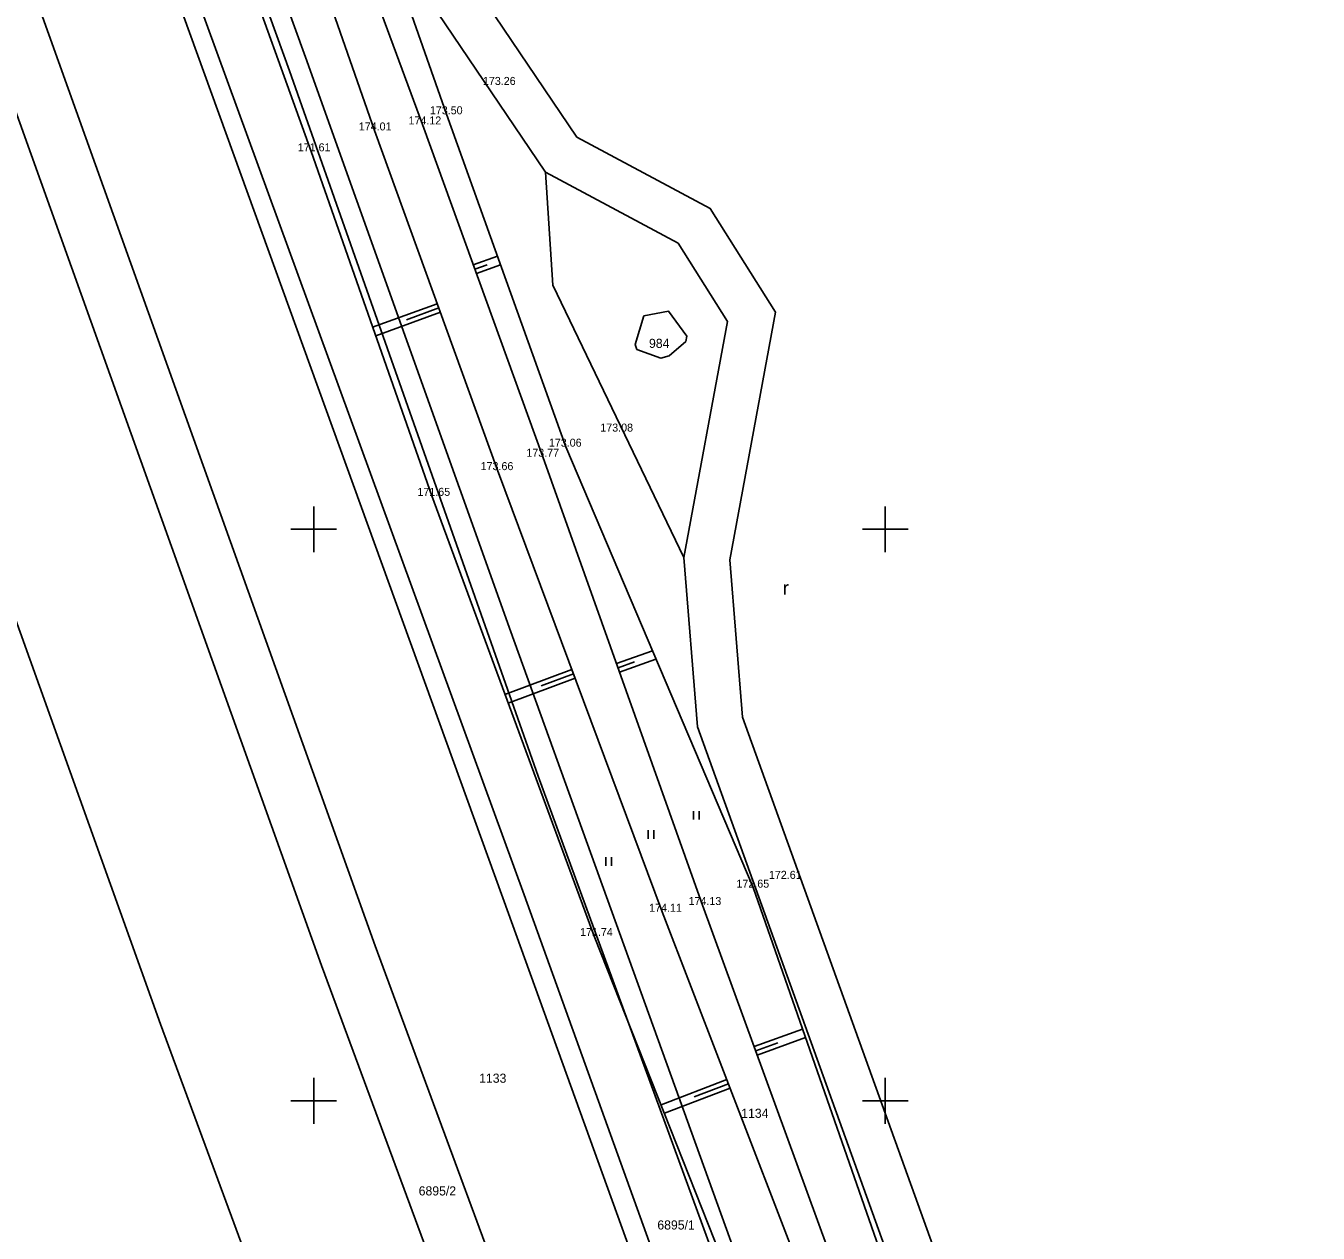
# Model space of a CAD drawing. Extents: x -612546 to -611926, y -1201932 to -1200444.
# Drawn here: x -612425.2 to -612312.1, y -1200761.6 to -1200656 of the extents above; entities that cross this region are included whole.
import ezdxf

# ---------------------------------------------------------------- set-up
doc = ezdxf.new("R2010")
doc.units = 0
for name, color, linetype in [('14 hrana pata svahu', 7, 'Continuous'), ('15 šrafy', 7, 'Continuous'), ('61 legenda křížky', 7, 'Continuous'), ('Hranice parcel', 7, 'Continuous'), ('Parcelní čísla', 7, 'Continuous'), ('Vnitřní kresba', 7, 'Continuous'), ('Vrstva 36', 7, 'Continuous'), ('výška bodu', 7, 'Continuous')]:
    doc.layers.add(name, color=color, linetype=linetype)

msp = doc.modelspace()

# ---------------------------------------------------------------- linework, layer by layer
at = {"layer": '14 hrana pata svahu'}
for points in [[(-612314.18, -1200875.11), (-612327.34, -1200838.97), (-612340.35, -1200802.82), (-612354.12, -1200765.43), (-612365.98, -1200732.87), (-612379.97, -1200693.65), (-612390.48, -1200664.58), (-612404.32, -1200627.17), (-612417.23, -1200591.7), (-612430.62, -1200555.12), (-612438.2, -1200533.09), (-612444.43, -1200520.21), (-612457.3, -1200503.64), (-612467.57, -1200490.07), (-612474.64, -1200478.9), (-612480.36, -1200469.57)], [(-612115.84, -1201111.42), (-612142.3, -1201080.92), (-612162.58, -1201054.92), (-612187.22, -1201025.94), (-612211.45, -1200996.73), (-612237.71, -1200968.13), (-612275.47, -1200925.26), (-612297.25, -1200898.18), (-612305.42, -1200888.34), (-612310.59, -1200874.11), (-612323.74, -1200837.38), (-612336.44, -1200801.43), (-612350.12, -1200764.09), (-612361.57, -1200731.35), (-612377.95, -1200692.77), (-612388.38, -1200663.69), (-612401.66, -1200625.89), (-612414.44, -1200590.59), (-612427.78, -1200553.92), (-612436.33, -1200532.1), (-612442.76, -1200519.02), (-612455.83, -1200502.43), (-612463.71, -1200487.36), (-612471.87, -1200478.15)], [(-612323.51, -1200877.98), (-612336.33, -1200841.94), (-612349.79, -1200805.31), (-612362.71, -1200767.78), (-612375.47, -1200735.58), (-612389.68, -1200697.07), (-612400.23, -1200666.93), (-612413.57, -1200629.83), (-612426, -1200594.78), (-612439.47, -1200557.74), (-612446.83, -1200536.72), (-612452.68, -1200524.51), (-612464.9, -1200509.43), (-612478.9, -1200492.91), (-612482.95, -1200488.23)], [(-612103.83, -1201136.8), (-612121.3, -1201116.23), (-612147.17, -1201085.43), (-612168.95, -1201059.31), (-612192.84, -1201031.05), (-612217.78, -1201001.78), (-612242.41, -1200972.81), (-612279.4, -1200929.44), (-612302.66, -1200902.78), (-612311.18, -1200891.48), (-612317.69, -1200875.87), (-612330.64, -1200840.25), (-612343.46, -1200803.61), (-612356.83, -1200766.41), (-612369.51, -1200733.46), (-612383.93, -1200694.82), (-612394.68, -1200665.1), (-612407.78, -1200627.56), (-612420.74, -1200592.57), (-612433.93, -1200555.79), (-612441.34, -1200534.1), (-612447.31, -1200522.04), (-612459.97, -1200505.78), (-612472.95, -1200489.44)]]:
    msp.add_lwpolyline(points, dxfattribs=at)
at = {"layer": '15 šrafy'}
for p, q in [((-612383.93, -1200676.1), (-612386.04, -1200676.87)), ((-612384.82, -1200676.85), (-612385.9, -1200677.24)), ((-612383.66, -1200676.86), (-612385.77, -1200677.62)), ((-612394.85, -1200682.3), (-612389.2, -1200680.26)), ((-612391.89, -1200681.66), (-612389.06, -1200680.63)), ((-612394.58, -1200683.06), (-612388.92, -1200681.01)), ((-612370.37, -1200710.62), (-612373.52, -1200711.74)), ((-612383.27, -1200714.45), (-612377.42, -1200712.27)), ((-612371.94, -1200711.6), (-612373.38, -1200712.12)), ((-612370.06, -1200711.36), (-612373.25, -1200712.49)), ((-612382.99, -1200715.2), (-612377.14, -1200713.02)), ((-612380.1, -1200713.69), (-612377.28, -1200712.64)), ((-612357.25, -1200743.72), (-612361.47, -1200745.25)), ((-612359.4, -1200744.93), (-612361.33, -1200745.63)), ((-612356.98, -1200744.47), (-612361.2, -1200746.01)), ((-612369.62, -1200750.35), (-612363.86, -1200748.13)), ((-612366.71, -1200749.66), (-612363.72, -1200748.51)), ((-612369.32, -1200751.09), (-612363.58, -1200748.88))]:
    msp.add_line(p, q, dxfattribs=at)
at = {"layer": '61 legenda křížky'}
for p, q in [((-612400, -1200702), (-612400, -1200698)), ((-612350, -1200702), (-612350, -1200698)), ((-612402, -1200700), (-612398, -1200700)), ((-612352, -1200700), (-612348, -1200700)), ((-612400, -1200752), (-612400, -1200748)), ((-612350, -1200752), (-612350, -1200748)), ((-612402, -1200750), (-612398, -1200750)), ((-612352, -1200750), (-612348, -1200750))]:
    msp.add_line(p, q, dxfattribs=at)
at = {"layer": 'Hranice parcel'}
for points in [[(-612492.54, -1200475.45), (-612489.15, -1200479.9), (-612487.29, -1200482.34), (-612470.55, -1200499.86), (-612454.58, -1200517.89), (-612449.12, -1200526.98), (-612444.88, -1200537.01), (-612400.71, -1200658.68), (-612382.76, -1200708.97), (-612320.94, -1200880.21), (-612316.28, -1200891.06), (-612307.37, -1200903.62), (-612259.67, -1200958.71), (-612214.29, -1201012.03), (-612172.62, -1201060.98), (-612120.7, -1201123.05), (-612073.85, -1201178.4), (-612068.4, -1201184.83), (-612055.42, -1201199.11), (-612044.78, -1201213.9), (-612040.42, -1201224.33), (-612036.87, -1201232.26)], [(-612053.63, -1201234.04), (-612049.72, -1201229.74), (-612051.31, -1201220.57), (-612058.28, -1201208.42), (-612073.89, -1201189.58), (-612079.31, -1201183.16), (-612173.25, -1201072.99), (-612266.53, -1200963.98), (-612308.11, -1200916.05), (-612320.05, -1200901.46), (-612326.37, -1200888.91), (-612352.76, -1200817.26), (-612383.45, -1200732.24), (-612424.46, -1200618.96), (-612450.75, -1200547.77), (-612455.75, -1200534.91), (-612462.05, -1200524.68), (-612490.01, -1200492.58), (-612497.19, -1200482.99)], [(-612467.57, -1200483.94), (-612457.95, -1200496.74), (-612450.95, -1200506.06), (-612439.8, -1200520.91), (-612432.5, -1200532.58), (-612389.16, -1200654.79), (-612379.73, -1200668.74)], [(-612504.85, -1200495.41), (-612492.66, -1200506.93), (-612476.27, -1200525), (-612462.43, -1200549.41), (-612435.01, -1200623.69), (-612394.62, -1200736.44), (-612362.83, -1200822.52), (-612336.91, -1200893.7), (-612329.46, -1200906.86), (-612317.29, -1200922.46), (-612274.72, -1200972.15), (-612181.97, -1201080.59), (-612092.56, -1201185.28), (-612096.16, -1201188.77)], [(-612098.55, -1201185.97), (-612185.77, -1201083.84), (-612278.52, -1200975.4), (-612321.16, -1200925.63), (-612333.63, -1200909.64), (-612341.47, -1200895.8), (-612367.52, -1200824.24), (-612399.32, -1200738.15), (-612439.71, -1200625.4), (-612466.98, -1200551.52), (-612480.35, -1200527.95), (-612496.23, -1200510.43), (-612507.54, -1200499.75)], [(-612424.14, -1200544.19), (-612385.56, -1200652.97), (-612376.97, -1200665.68), (-612365.31, -1200671.92), (-612359.59, -1200681.01), (-612363.6, -1200702.67), (-612362.5, -1200716.42), (-612304.9, -1200876.31), (-612299.88, -1200886.48), (-612289.63, -1200899.21), (-612225.19, -1200972.6)], [(-612480.63, -1200557.86), (-612453.81, -1200630.53), (-612413.42, -1200743.28), (-612381.61, -1200829.41), (-612355.13, -1200902.11), (-612346.14, -1200918), (-612332.78, -1200935.12), (-612289.91, -1200985.15), (-612197.17, -1201093.58), (-612109.96, -1201195.71)], [(-612367.63, -1200702.46), (-612363.81, -1200681.82), (-612368.13, -1200674.95), (-612379.73, -1200668.74)], [(-612379.73, -1200668.74), (-612379.09, -1200678.65), (-612367.63, -1200702.46)], [(-612367.63, -1200702.46), (-612366.44, -1200717.27), (-612308.59, -1200877.88), (-612303.27, -1200888.65), (-612292.69, -1200901.79), (-612203.37, -1201003.51), (-612163.72, -1201050.75), (-612139.89, -1201080.24), (-612084.23, -1201147.54), (-612068.31, -1201163.86)]]:
    msp.add_lwpolyline(points, dxfattribs=at)
at = {"layer": 'Vnitřní kresba'}
for p, q in [((-612445.86, -1200537.76), (-612402.12, -1200659.9)), ((-612402.12, -1200659.9), (-612380.36, -1200721.61)), ((-612380.36, -1200721.61), (-612321.45, -1200882.64))]:
    msp.add_line(p, q, dxfattribs=at)
for points in [[(-612077.99, -1201182.01), (-612172.2, -1201072.72), (-612264.55, -1200963.36), (-612306.48, -1200914.97), (-612319.15, -1200900.26), (-612324.5, -1200887.86), (-612350.35, -1200818.69), (-612381.6, -1200731.97), (-612422.84, -1200618.87), (-612449.81, -1200544.11), (-612465.28, -1200517.45), (-612482.79, -1200495.64), (-612497.19, -1200482.99)], [(-612371.12, -1200681.31), (-612371.88, -1200683.84), (-612371.73, -1200684.26), (-612369.64, -1200685.02), (-612368.9, -1200684.83), (-612367.44, -1200683.56), (-612367.35, -1200683.09), (-612368.96, -1200680.92), (-612371.12, -1200681.31)]]:
    msp.add_lwpolyline(points, dxfattribs=at)
at = {"layer": 'Vrstva 36'}
for p, q in [((-612366.79, -1200725.4), (-612366.79, -1200724.65)), ((-612366.29, -1200725.4), (-612366.29, -1200724.65)), ((-612370.74, -1200727.08), (-612370.74, -1200726.33)), ((-612370.24, -1200727.08), (-612370.24, -1200726.33)), ((-612374.44, -1200729.43), (-612374.44, -1200728.68)), ((-612373.94, -1200729.43), (-612373.94, -1200728.68))]:
    msp.add_line(p, q, dxfattribs=at)

# ---------------------------------------------------------------- texts
at = {"layer": 'Parcelní čísla'}
for s, p in [('984', (-612370.67, -1200684.13)), ('1133', (-612385.53, -1200748.42)), ('1134', (-612362.6, -1200751.49)), ('6895/2', (-612390.82, -1200758.28)), ('6895/1', (-612369.94, -1200761.26))]:
    msp.add_text(s, height=0.8, dxfattribs=at).set_placement(p)
at = {"layer": 'Vrstva 36'}
msp.add_text('r', height=1.2, dxfattribs=at).set_placement((-612358.97, -1200705.73))
at = {"layer": 'výška bodu'}
for s, p in [('173.26', (-612385.2, -1200661.12)), ('173.50', (-612389.84, -1200663.69)), ('174.01', (-612396.06, -1200665.1)), ('174.12', (-612391.71, -1200664.58)), ('171.61', (-612401.4, -1200666.93)), ('173.08', (-612374.93, -1200691.45)), ('173.77', (-612381.4, -1200693.65)), ('173.06', (-612379.43, -1200692.77)), ('173.66', (-612385.4, -1200694.82)), ('171.65', (-612390.93, -1200697.07)), ('172.61', (-612360.18, -1200730.58)), ('172.65', (-612363.02, -1200731.35)), ('174.13', (-612367.21, -1200732.87)), ('174.11', (-612370.66, -1200733.46)), ('171.74', (-612376.7, -1200735.58))]:
    msp.add_text(s, height=0.7, dxfattribs=at).set_placement(p)

doc.saveas('drawing.dxf')
